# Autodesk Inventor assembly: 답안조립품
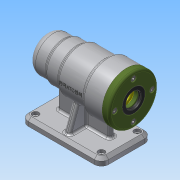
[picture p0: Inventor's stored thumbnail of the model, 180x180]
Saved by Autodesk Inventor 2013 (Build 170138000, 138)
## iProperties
Created: 2016-06
Part Number: 답안조립품
Document SubType Name: Assembly
Designer: Administrator
Author: Administrator
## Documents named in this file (6)
- C:\Users\Administrator\Desktop\460608V1007\답안조립품.iam
- C:\Users\Administrator\Desktop\460608V1007\본체.ipt
- C:\Users\Administrator\Desktop\460608V1007\베어링 6004.ipt
- C:\Users\Administrator\Desktop\460608V1007\커버.ipt
- C:\Users\Administrator\Desktop\460608V1007\볼트 M4 x 12.ipt
- C:\Users\Administrator\Desktop\460608V1007\오일 실.ipt
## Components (4 placed, 1 different names)
1. ISO 4762 M4 x 12:1
2. ISO 4762 M4 x 12:2
3. ISO 4762 M4 x 12:3
4. ISO 4762 M4 x 12:4
